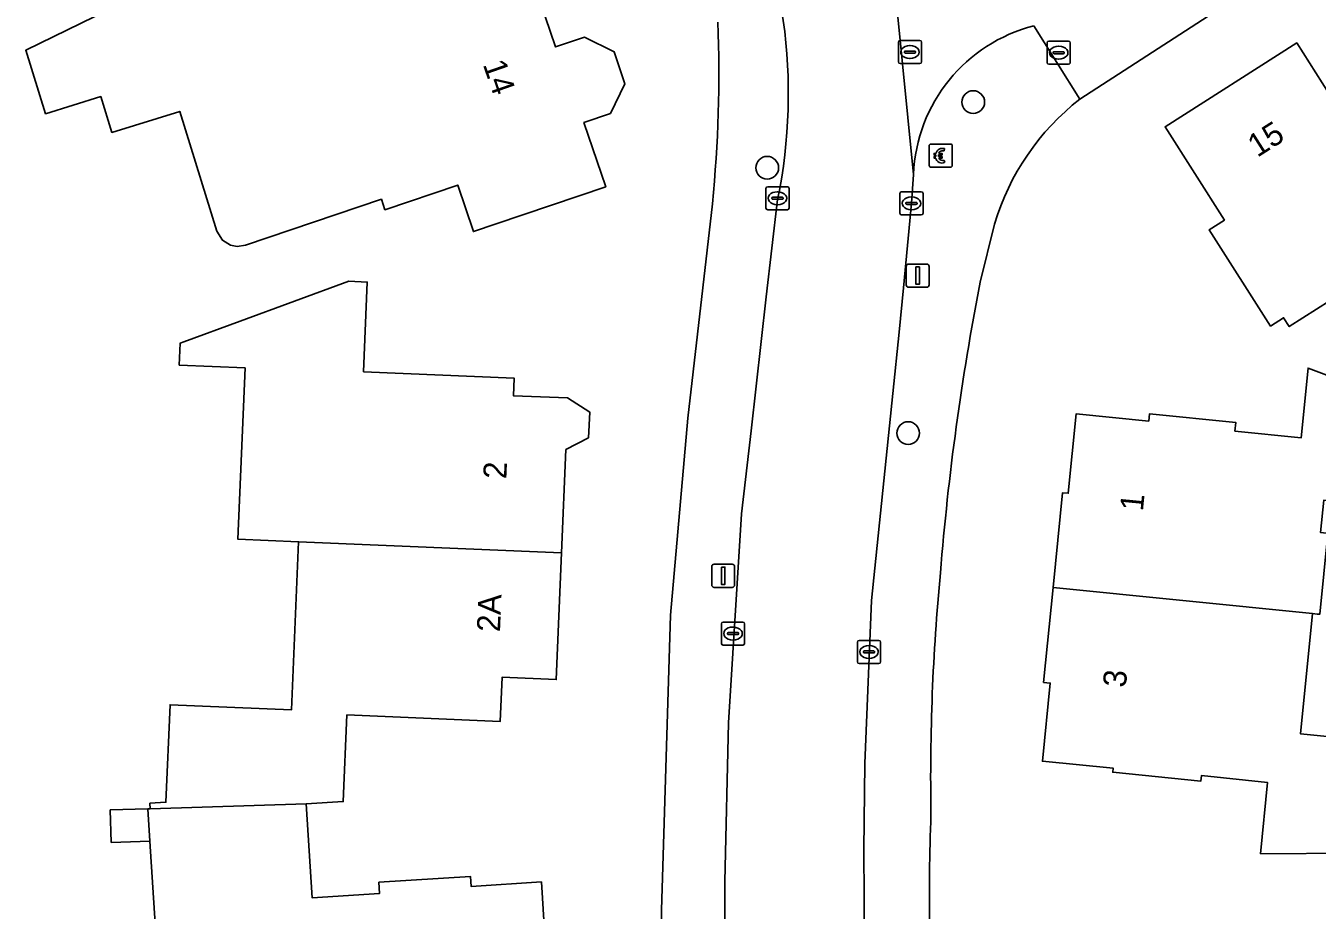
# Model space of a CAD drawing. Extents: x 161347 to 161881, y 382161 to 382804.
# Drawn here: x 161441.9 to 161497.7, y 382360.9 to 382399.1 of the extents above; entities that cross this region are included whole.
import ezdxf

# ---------------------------------------------------------------- set-up
doc = ezdxf.new("R2010")
doc.units = 0
for name, color, linetype in [('IMGEO_Betaalautomaat', 7, 'Continuous'), ('IMGEO_Boom', 7, 'Continuous'), ('IMGEO_Brandkraan', 7, 'Continuous'), ('IMGEO_Erf', 7, 'Continuous'), ('IMGEO_Kolk', 7, 'Continuous'), ('IMGEO_Lichtmast', 7, 'Continuous'), ('IMGEO_Pand', 7, 'Continuous'), ('IMGEO_Pand_nummerreeks', 7, 'Continuous'), ('IMGEO_Rijbaan_lokaal_open', 7, 'Continuous'), ('IMGEO_Rioolput', 7, 'Continuous'), ('IMGEO_Voetpad_open', 7, 'Continuous')]:
    doc.layers.add(name, color=color, linetype=linetype)

msp = doc.modelspace()

# ---------------------------------------------------------------- linework, layer by layer
at = {"layer": 'IMGEO_Betaalautomaat'}
for p, q in [((161481.039, 382393.984), (161481.88, 382393.984)), ((161481.88, 382393.984), (161481.039, 382393.984)), ((161480.964, 382393.06), (161480.964, 382393.901)), ((161480.964, 382393.901), (161480.964, 382393.06)), ((161481.247, 382393.448), (161481.247, 382393.516)), ((161481.368, 382393.516), (161481.368, 382393.448)), ((161481.626, 382393.789), (161481.609, 382393.689)), ((161481.963, 382393.91), (161481.963, 382393.069)), ((161481.963, 382393.069), (161481.963, 382393.91)), ((161481.889, 382392.985), (161481.048, 382392.985)), ((161481.048, 382392.985), (161481.889, 382392.985)), ((161481.613, 382393.283), (161481.635, 382393.196))]:
    msp.add_line(p, q, dxfattribs=at)
for points in [[(161481.247, 382393.516), (161481.178, 382393.516), (161481.178, 382393.585), (161481.257, 382393.585)], [(161481.252, 382393.379), (161481.178, 382393.379), (161481.178, 382393.448), (161481.247, 382393.448)], [(161481.379, 382393.585), (161481.526, 382393.585), (161481.526, 382393.516), (161481.368, 382393.516)], [(161481.368, 382393.448), (161481.526, 382393.448), (161481.526, 382393.379), (161481.382, 382393.379)]]:
    msp.add_lwpolyline(points, dxfattribs=at)
for centre, radius, start, end in [((161481.042, 382393.907), 0.0779, 92.4484, 184.2845), ((161481.042, 382393.907), 0.0779, 92.4484, 184.2845), ((161481.886, 382393.907), 0.0779, 2.4484, 94.2845), ((161481.886, 382393.907), 0.0779, 2.4484, 94.2845), ((161481.54, 382393.509), 0.293, 73.014, 165.0139), ((161481.546, 382393.522), 0.179, 69.3236, 159.5683), ((161481.042, 382393.063), 0.0779, 182.4484, 274.2845), ((161481.042, 382393.063), 0.0779, 182.4484, 274.2845), ((161481.513, 382393.434), 0.267, 191.8096, 297.0389), ((161481.546, 382393.449), 0.179, 202.7625, 291.8693), ((161481.886, 382393.063), 0.0779, 272.4484, 4.2845), ((161481.886, 382393.063), 0.0779, 272.4484, 4.2845)]:
    msp.add_arc(centre, radius, start, end, dxfattribs=at)
at = {"layer": 'IMGEO_Boom'}
for centre in [(161482.871, 382395.802), (161473.963, 382392.963), (161480.054, 382381.496)]:
    msp.add_circle(centre, 0.489, dxfattribs=at)
at = {"layer": 'IMGEO_Brandkraan'}
for p, q in [((161486.065, 382397.51), (161486.065, 382398.362)), ((161486.14, 382398.436), (161486.992, 382398.436)), ((161486.324, 382397.93), (161486.324, 382397.942)), ((161486.762, 382397.893), (161486.364, 382397.893)), ((161486.367, 382397.979), (161486.765, 382397.979)), ((161486.553, 382398.216), (161486.578, 382398.216)), ((161486.808, 382397.942), (161486.808, 382397.93)), ((161487.066, 382398.362), (161487.066, 382397.51)), ((161486.992, 382397.436), (161486.14, 382397.436)), ((161486.576, 382397.656), (161486.551, 382397.656))]:
    msp.add_line(p, q, dxfattribs=at)
for points in [[(161486.065, 382397.51), (161486.065, 382398.362)], [(161486.14, 382398.436), (161486.992, 382398.436)], [(161487.066, 382398.362), (161487.066, 382397.51)], [(161486.992, 382397.436), (161486.14, 382397.436)]]:
    msp.add_lwpolyline(points, dxfattribs=at)
for centre, radius, start, end in [((161486.142, 382398.36), 0.0765, 91.552, 178.448), ((161486.142, 382398.36), 0.0765, 91.552, 178.448), ((161486.364, 382397.939), 0.0403, 85.8775, 175.7526), ((161486.361, 382397.929), 0.0366, 178.938, 274.7102), ((161486.765, 382397.936), 0.043, 264.8664, 352.4533), ((161486.769, 382397.941), 0.0386, 1.7309, 96.639), ((161486.99, 382398.36), 0.0765, 1.552, 88.448), ((161486.99, 382398.36), 0.0765, 1.552, 88.448), ((161486.142, 382397.512), 0.0765, 181.552, 268.448), ((161486.142, 382397.512), 0.0765, 181.552, 268.448), ((161486.99, 382397.512), 0.0765, 271.552, 358.448), ((161486.99, 382397.512), 0.0765, 271.552, 358.448)]:
    msp.add_arc(centre, radius, start, end, dxfattribs=at)
for centre, major_axis, ratio, start_param, end_param in [((161486.552, 382397.936), (-0.387, 0.002), 0.722429, 4.712389, 7.853982), ((161486.577, 382397.936), (-0.39, 0.002), 0.717154, 1.570796, 4.712389)]:
    msp.add_ellipse(centre, major_axis=major_axis, ratio=ratio, start_param=start_param, end_param=end_param, dxfattribs=at)
at = {"layer": 'IMGEO_Erf'}
for points in [[(161617.144, 382396.335), (161617.418, 382397.853), (161603.267, 382420.926), (161601.482, 382423.837), (161585.851, 382449.323), (161572.419, 382451.387), (161564.764, 382446.042), (161558.459, 382441.915), (161500, 382404.037), (161487.478, 382395.924)], [(161463.01, 382403.497), (161464.811, 382398.182), (161466.063, 382398.606), (161467.338, 382397.976), (161467.81, 382396.584), (161467.178, 382395.304), (161466.037, 382394.917), (161466.977, 382392.145), (161462.242, 382390.54), (161461.258, 382390.207), (161460.577, 382392.215), (161457.433, 382391.149), (161457.279, 382391.604), (161451.403, 382389.612), (161451.041, 382389.561), (161450.751, 382389.62), (161450.413, 382389.832), (161450.165, 382390.222), (161448.556, 382395.4), (161445.624, 382394.489), (161445.143, 382396.036), (161442.756, 382395.294), (161441.902, 382398.039), (161450.849, 382402.431)], [(161469.78, 382373.623), (161470.522, 382382.134), (161471.59, 382391.404)], [(161483.786, 382390.531), (161483.173, 382388.018)], [(161447.592, 382358.746), (161447.271, 382363.854), (161445.597, 382363.802), (161445.553, 382365.206), (161447.183, 382365.257), (161447.284, 382365.26), (161447.269, 382365.496), (161447.96, 382365.539), (161448.137, 382369.757), (161453.394, 382369.537), (161453.698, 382376.796), (161451.074, 382376.906), (161451.384, 382384.314), (161448.535, 382384.433), (161448.575, 382385.375), (161448.732, 382385.433), (161451.176, 382386.331), (161455.869, 382388.055), (161456.668, 382388.021), (161456.505, 382384.145), (161463.018, 382383.871), (161462.986, 382383.112), (161465.323, 382383.015), (161466.284, 382382.404), (161466.237, 382381.297), (161465.256, 382380.784), (161465.07, 382376.321), (161464.842, 382370.842), (161462.497, 382370.94), (161462.417, 382369.037), (161455.784, 382369.315), (161455.627, 382365.57), (161454.029, 382365.47), (161454.282, 382361.415), (161457.201, 382361.599), (161457.17, 382362.086), (161461.129, 382362.334), (161461.156, 382361.903), (161464.198, 382362.095), (161464.435, 382358.327)], [(161499.257, 382363.337), (161495.296, 382363.317), (161495.599, 382366.388), (161492.736, 382366.691), (161492.712, 382366.457), (161488.905, 382366.837), (161488.922, 382367.007), (161485.86, 382367.313), (161486.198, 382370.692), (161485.914, 382370.72), (161486.324, 382374.818), (161486.734, 382378.916), (161486.978, 382378.892), (161487.322, 382382.33), (161490.457, 382382.017), (161490.488, 382382.326), (161494.22, 382381.953), (161494.183, 382381.583), (161497.046, 382381.288), (161497.352, 382384.306), (161500, 382383.308)], [(161469.389, 382360.877), (161469.78, 382373.623)], [(161497.793, 382373.671), (161497.741, 382373.676), (161497.542, 382373.696), (161497.022, 382368.493), (161499.745, 382368.221)]]:
    msp.add_lwpolyline(points, dxfattribs=at)
msp.add_lwpolyline([(161502.083, 382392.021), (161504.368, 382388.437), (161502.582, 382387.27), (161500.724, 382386.056), (161500, 382387.174), (161499.482, 382387.974), (161496.532, 382386.095), (161496.289, 382386.477), (161495.731, 382386.121), (161493.078, 382390.285), (161493.735, 382390.704), (161491.166, 382394.735), (161496.857, 382398.36), (161498.783, 382395.337), (161500, 382396.112), (161500.681, 382396.546), (161503.137, 382392.692)], close=True, dxfattribs=at)
for centre, radius, start, end in [((161415.607, 382397.014), 56.263, 354.2771, 2.2772), ((161494.127, 382387.412), 10.801, 127.9943, 163.2153), ((161593.048, 382366.576), 111.948, 168.95745, 175.45076), ((161573.502, 382366.61), 92.473, 174.51109, 180.99743), ((161557.326, 382361.781), 76.351, 177.58362, 185.0968), ((161553.635, 382359.287), 84.261, 178.91872, 187.12135)]:
    msp.add_arc(centre, radius, start, end, dxfattribs=at)
at = {"layer": 'IMGEO_Kolk'}
for p, q in [((161473.906, 382391.218), (161473.906, 382392.07)), ((161473.981, 382392.144), (161474.833, 382392.144)), ((161474.394, 382391.924), (161474.419, 382391.924)), ((161474.907, 382392.07), (161474.907, 382391.218)), ((161479.697, 382390.998), (161479.697, 382391.85)), ((161479.772, 382391.924), (161480.624, 382391.924)), ((161480.698, 382391.85), (161480.698, 382390.998)), ((161474.165, 382391.638), (161474.165, 382391.65)), ((161474.603, 382391.601), (161474.205, 382391.601)), ((161474.208, 382391.687), (161474.606, 382391.687)), ((161474.417, 382391.364), (161474.392, 382391.364)), ((161474.649, 382391.65), (161474.649, 382391.638)), ((161479.956, 382391.418), (161479.956, 382391.43)), ((161480.394, 382391.381), (161479.996, 382391.381)), ((161479.999, 382391.467), (161480.397, 382391.467)), ((161480.185, 382391.704), (161480.21, 382391.704)), ((161480.44, 382391.43), (161480.44, 382391.418)), ((161474.833, 382391.144), (161473.981, 382391.144)), ((161480.624, 382390.924), (161479.772, 382390.924)), ((161480.208, 382391.144), (161480.183, 382391.144)), ((161472.058, 382373.33), (161472.91, 382373.33)), ((161471.983, 382372.404), (161471.983, 382373.256)), ((161472.242, 382372.824), (161472.242, 382372.836)), ((161472.68, 382372.787), (161472.282, 382372.787)), ((161472.285, 382372.873), (161472.683, 382372.873)), ((161472.471, 382373.11), (161472.496, 382373.11)), ((161472.726, 382372.836), (161472.726, 382372.824)), ((161472.984, 382373.256), (161472.984, 382372.404)), ((161472.91, 382372.33), (161472.058, 382372.33)), ((161472.494, 382372.55), (161472.469, 382372.55)), ((161477.863, 382371.61), (161477.863, 382372.462)), ((161477.938, 382372.536), (161478.79, 382372.536)), ((161478.351, 382372.316), (161478.376, 382372.316)), ((161478.864, 382372.462), (161478.864, 382371.61)), ((161478.122, 382372.03), (161478.122, 382372.042)), ((161478.56, 382371.993), (161478.162, 382371.993)), ((161478.165, 382372.079), (161478.563, 382372.079)), ((161478.374, 382371.756), (161478.349, 382371.756)), ((161478.606, 382372.042), (161478.606, 382372.03)), ((161478.79, 382371.536), (161477.938, 382371.536))]:
    msp.add_line(p, q, dxfattribs=at)
for points in [[(161473.906, 382391.218), (161473.906, 382392.07)], [(161473.981, 382392.144), (161474.833, 382392.144)], [(161474.907, 382392.07), (161474.907, 382391.218)], [(161479.697, 382390.998), (161479.697, 382391.85)], [(161479.772, 382391.924), (161480.624, 382391.924)], [(161480.698, 382391.85), (161480.698, 382390.998)], [(161474.833, 382391.144), (161473.981, 382391.144)], [(161480.624, 382390.924), (161479.772, 382390.924)], [(161472.058, 382373.33), (161472.91, 382373.33)], [(161471.983, 382372.404), (161471.983, 382373.256)], [(161472.984, 382373.256), (161472.984, 382372.404)], [(161472.91, 382372.33), (161472.058, 382372.33)], [(161477.863, 382371.61), (161477.863, 382372.462)], [(161477.938, 382372.536), (161478.79, 382372.536)], [(161478.864, 382372.462), (161478.864, 382371.61)], [(161478.79, 382371.536), (161477.938, 382371.536)]]:
    msp.add_lwpolyline(points, dxfattribs=at)
for centre, radius, start, end in [((161473.983, 382392.068), 0.0765, 91.552, 178.448), ((161473.983, 382392.068), 0.0765, 91.552, 178.448), ((161474.831, 382392.068), 0.0765, 1.552, 88.448), ((161474.831, 382392.068), 0.0765, 1.552, 88.448), ((161479.774, 382391.848), 0.0765, 91.552, 178.448), ((161479.774, 382391.848), 0.0765, 91.552, 178.448), ((161480.622, 382391.848), 0.0765, 1.552, 88.448), ((161480.622, 382391.848), 0.0765, 1.552, 88.448), ((161473.983, 382391.22), 0.0765, 181.552, 268.448), ((161473.983, 382391.22), 0.0765, 181.552, 268.448), ((161474.205, 382391.647), 0.0403, 85.8775, 175.7526), ((161474.202, 382391.637), 0.0366, 178.938, 274.7102), ((161474.606, 382391.644), 0.043, 264.8664, 352.4533), ((161474.61, 382391.649), 0.0386, 1.7309, 96.639), ((161474.831, 382391.22), 0.0765, 271.552, 358.448), ((161474.831, 382391.22), 0.0765, 271.552, 358.448), ((161479.996, 382391.427), 0.0403, 85.8775, 175.7526), ((161479.993, 382391.417), 0.0366, 178.938, 274.7102), ((161480.397, 382391.424), 0.043, 264.8664, 352.4533), ((161480.401, 382391.429), 0.0386, 1.7309, 96.639), ((161479.774, 382391), 0.0765, 181.552, 268.448), ((161479.774, 382391), 0.0765, 181.552, 268.448), ((161480.622, 382391), 0.0765, 271.552, 358.448), ((161480.622, 382391), 0.0765, 271.552, 358.448), ((161472.06, 382373.254), 0.0765, 91.552, 178.448), ((161472.06, 382373.254), 0.0765, 91.552, 178.448), ((161472.908, 382373.254), 0.0765, 1.552, 88.448), ((161472.908, 382373.254), 0.0765, 1.552, 88.448), ((161472.282, 382372.833), 0.0403, 85.8775, 175.7526), ((161472.279, 382372.823), 0.0366, 178.938, 274.7102), ((161472.683, 382372.83), 0.043, 264.8664, 352.4533), ((161472.687, 382372.835), 0.0386, 1.7309, 96.639), ((161472.06, 382372.406), 0.0765, 181.552, 268.448), ((161472.06, 382372.406), 0.0765, 181.552, 268.448), ((161472.908, 382372.406), 0.0765, 271.552, 358.448), ((161472.908, 382372.406), 0.0765, 271.552, 358.448), ((161477.94, 382372.46), 0.0765, 91.552, 178.448), ((161477.94, 382372.46), 0.0765, 91.552, 178.448), ((161478.788, 382372.46), 0.0765, 1.552, 88.448), ((161478.788, 382372.46), 0.0765, 1.552, 88.448), ((161478.162, 382372.039), 0.0403, 85.8775, 175.7526), ((161478.159, 382372.029), 0.0366, 178.938, 274.7102), ((161478.563, 382372.036), 0.043, 264.8664, 352.4533), ((161478.567, 382372.041), 0.0386, 1.7309, 96.639), ((161477.94, 382371.612), 0.0765, 181.552, 268.448), ((161477.94, 382371.612), 0.0765, 181.552, 268.448), ((161478.788, 382371.612), 0.0765, 271.552, 358.448), ((161478.788, 382371.612), 0.0765, 271.552, 358.448)]:
    msp.add_arc(centre, radius, start, end, dxfattribs=at)
for centre, major_axis, ratio, start_param, end_param in [((161474.393, 382391.644), (-0.387, 0.002), 0.722429, 4.712389, 7.853982), ((161474.418, 382391.644), (-0.39, 0.002), 0.717154, 1.570796, 4.712389), ((161480.184, 382391.424), (-0.387, 0.002), 0.722429, 4.712389, 7.853982), ((161480.209, 382391.424), (-0.39, 0.002), 0.717154, 1.570796, 4.712389), ((161472.47, 382372.83), (-0.387, 0.002), 0.722429, 4.712389, 7.853982), ((161472.495, 382372.83), (-0.39, 0.002), 0.717154, 1.570796, 4.712389), ((161478.35, 382372.036), (-0.387, 0.002), 0.722429, 4.712389, 7.853982), ((161478.375, 382372.036), (-0.39, 0.002), 0.717154, 1.570796, 4.712389)]:
    msp.add_ellipse(centre, major_axis=major_axis, ratio=ratio, start_param=start_param, end_param=end_param, dxfattribs=at)
at = {"layer": 'IMGEO_Lichtmast'}
for p, q in [((161479.973, 382387.9), (161479.973, 382388.7)), ((161479.973, 382388.7), (161479.973, 382387.9)), ((161480.073, 382388.8), (161480.863, 382388.8)), ((161480.863, 382388.8), (161480.073, 382388.8)), ((161480.963, 382388.7), (161480.963, 382387.9)), ((161480.963, 382387.9), (161480.963, 382388.7)), ((161480.863, 382387.8), (161480.073, 382387.8)), ((161480.073, 382387.8), (161480.863, 382387.8)), ((161471.562, 382374.929), (161471.562, 382375.729)), ((161471.562, 382375.729), (161471.562, 382374.929)), ((161471.662, 382375.829), (161472.452, 382375.829)), ((161472.452, 382375.829), (161471.662, 382375.829)), ((161472.552, 382375.729), (161472.552, 382374.929)), ((161472.552, 382374.929), (161472.552, 382375.729)), ((161472.452, 382374.829), (161471.662, 382374.829)), ((161471.662, 382374.829), (161472.452, 382374.829))]:
    msp.add_line(p, q, dxfattribs=at)
for points in [[(161480.393, 382388.675), (161480.543, 382388.675), (161480.543, 382387.925), (161480.393, 382387.925), (161480.393, 382388.675)], [(161471.982, 382375.704), (161472.132, 382375.704), (161472.132, 382374.954), (161471.982, 382374.954), (161471.982, 382375.704)]]:
    msp.add_lwpolyline(points, dxfattribs=at)
for centre, start, end in [((161480.073, 382388.7), 90, 180), ((161480.073, 382388.7), 90, 180), ((161480.863, 382388.7), 0, 90), ((161480.863, 382388.7), 360, 90), ((161480.073, 382387.9), 180, 270), ((161480.073, 382387.9), 180, 270), ((161480.863, 382387.9), 270, 0), ((161480.863, 382387.9), 270, 0), ((161471.662, 382375.729), 90, 180), ((161471.662, 382375.729), 90, 180), ((161472.452, 382375.729), 0, 90), ((161472.452, 382375.729), 360, 90), ((161471.662, 382374.929), 180, 270), ((161471.662, 382374.929), 180, 270), ((161472.452, 382374.929), 270, 0), ((161472.452, 382374.929), 270, 0)]:
    msp.add_arc(centre, 0.1, start, end, dxfattribs=at)
at = {"layer": 'IMGEO_Pand'}
msp.add_lwpolyline([(161450.849, 382402.431), (161441.902, 382398.039), (161442.756, 382395.294), (161445.143, 382396.036), (161445.624, 382394.489), (161448.556, 382395.4), (161450.165, 382390.222), (161450.413, 382389.832), (161450.751, 382389.62), (161451.041, 382389.561), (161451.403, 382389.612), (161457.279, 382391.604), (161457.433, 382391.149), (161460.577, 382392.215), (161461.258, 382390.207), (161462.242, 382390.54), (161466.977, 382392.145), (161466.037, 382394.917), (161467.178, 382395.304), (161467.81, 382396.584), (161467.338, 382397.976), (161466.063, 382398.606), (161464.811, 382398.182), (161463.01, 382403.497)], dxfattribs=at)
for points in [[(161503.137, 382392.692), (161500.681, 382396.546), (161500, 382396.112), (161498.783, 382395.337), (161496.857, 382398.36), (161491.166, 382394.735), (161493.735, 382390.704), (161493.078, 382390.285), (161495.731, 382386.121), (161496.289, 382386.477), (161496.532, 382386.095), (161499.482, 382387.974), (161500, 382387.174), (161500.724, 382386.056), (161502.582, 382387.27), (161504.368, 382388.437), (161502.083, 382392.021)], [(161463.018, 382383.871), (161456.505, 382384.145), (161456.668, 382388.021), (161455.869, 382388.055), (161451.176, 382386.331), (161448.732, 382385.433), (161448.575, 382385.375), (161448.535, 382384.433), (161451.384, 382384.314), (161451.074, 382376.906), (161453.698, 382376.796), (161465.07, 382376.321), (161465.256, 382380.784), (161466.237, 382381.297), (161466.284, 382382.404), (161465.323, 382383.015), (161462.986, 382383.112)], [(161501.136, 382382.88), (161500, 382383.308), (161497.352, 382384.306), (161497.046, 382381.288), (161494.183, 382381.583), (161494.22, 382381.953), (161490.488, 382382.326), (161490.457, 382382.017), (161487.322, 382382.33), (161486.978, 382378.892), (161486.734, 382378.916), (161486.324, 382374.818), (161497.542, 382373.696), (161497.741, 382373.676), (161497.793, 382373.671), (161497.852, 382373.665), (161498.203, 382377.162), (161498.144, 382377.168), (161497.892, 382377.195), (161498.033, 382378.6), (161500, 382378.387), (161500.691, 382378.312)], [(161465.07, 382376.321), (161453.698, 382376.796), (161453.394, 382369.537), (161448.137, 382369.757), (161447.96, 382365.539), (161447.269, 382365.496), (161447.284, 382365.26), (161454.029, 382365.47), (161455.627, 382365.57), (161455.784, 382369.315), (161462.417, 382369.037), (161462.497, 382370.94), (161464.842, 382370.842)], [(161486.324, 382374.818), (161485.914, 382370.72), (161486.198, 382370.692), (161485.86, 382367.313), (161488.922, 382367.007), (161488.905, 382366.837), (161492.712, 382366.457), (161492.736, 382366.691), (161495.599, 382366.388), (161495.296, 382363.317), (161499.257, 382363.337), (161499.745, 382368.221), (161497.022, 382368.493), (161497.542, 382373.696)], [(161447.183, 382365.257), (161445.553, 382365.206), (161445.597, 382363.802), (161447.271, 382363.854)], [(161454.029, 382365.47), (161447.284, 382365.26), (161447.183, 382365.257), (161447.271, 382363.854), (161447.592, 382358.746), (161447.699, 382358.647), (161448.456, 382357.949), (161451.747, 382358.156), (161452, 382354.124), (161454.377, 382354.255), (161464.698, 382354.898), (161464.645, 382355.738), (161465.298, 382356.172), (161465.186, 382357.953), (161464.435, 382358.327), (161464.198, 382362.095), (161461.156, 382361.903), (161461.129, 382362.334), (161457.17, 382362.086), (161457.201, 382361.599), (161454.282, 382361.415)]]:
    msp.add_lwpolyline(points, close=True, dxfattribs=at)
at = {"layer": 'IMGEO_Rijbaan_lokaal_open'}
for points in [[(161478.141, 382363.489), (161478.179, 382367.212), (161478.467, 382374.26), (161479.39, 382383.203), (161479.664, 382385.857), (161479.848, 382387.77), (161480.126, 382390.67), (161480.197, 382391.427), (161480.29, 382392.675), (161478.84, 382407.183)], [(161478.84, 382407.183), (161480.29, 382392.675)], [(161474.412, 382391.584), (161473.921, 382387.39), (161473.27, 382381.594), (161472.852, 382378.01), (161472.288, 382368.966), (161472.129, 382362.118)], [(161478.913, 382349.703), (161478.847, 382350.23), (161478.529, 382353.479), (161478.171, 382359.336), (161478.141, 382363.489)]]:
    msp.add_lwpolyline(points, dxfattribs=at)
for centre, radius, start, end in [((161451.842, 382396.174), 23.032, 348.5059, 27.2322), ((161487.188, 382392.403), 6.903, 104.1787, 177.7418), ((161565.952, 382361.125), 93.828, 179.39336, 187.11372)]:
    msp.add_arc(centre, radius, start, end, dxfattribs=at)
at = {"layer": 'IMGEO_Rioolput'}
for p, q in [((161479.708, 382398.465), (161480.56, 382398.465)), ((161479.633, 382397.539), (161479.633, 382398.391)), ((161479.892, 382397.959), (161479.892, 382397.971)), ((161480.33, 382397.922), (161479.932, 382397.922)), ((161479.935, 382398.008), (161480.333, 382398.008)), ((161480.121, 382398.245), (161480.146, 382398.245)), ((161480.376, 382397.971), (161480.376, 382397.959)), ((161480.634, 382398.391), (161480.634, 382397.539)), ((161480.56, 382397.465), (161479.708, 382397.465)), ((161480.144, 382397.685), (161480.119, 382397.685))]:
    msp.add_line(p, q, dxfattribs=at)
for points in [[(161479.708, 382398.465), (161480.56, 382398.465)], [(161479.633, 382397.539), (161479.633, 382398.391)], [(161480.634, 382398.391), (161480.634, 382397.539)], [(161480.56, 382397.465), (161479.708, 382397.465)]]:
    msp.add_lwpolyline(points, dxfattribs=at)
for centre, radius, start, end in [((161479.71, 382398.389), 0.0765, 91.552, 178.448), ((161479.71, 382398.389), 0.0765, 91.552, 178.448), ((161480.558, 382398.389), 0.0765, 1.552, 88.448), ((161480.558, 382398.389), 0.0765, 1.552, 88.448), ((161479.932, 382397.968), 0.0403, 85.8775, 175.7526), ((161479.929, 382397.958), 0.0366, 178.938, 274.7102), ((161480.333, 382397.965), 0.043, 264.8664, 352.4533), ((161480.337, 382397.97), 0.0386, 1.7309, 96.639), ((161479.71, 382397.541), 0.0765, 181.552, 268.448), ((161479.71, 382397.541), 0.0765, 181.552, 268.448), ((161480.558, 382397.541), 0.0765, 271.552, 358.448), ((161480.558, 382397.541), 0.0765, 271.552, 358.448)]:
    msp.add_arc(centre, radius, start, end, dxfattribs=at)
for centre, major_axis, ratio, start_param, end_param in [((161480.12, 382397.965), (-0.387, 0.002), 0.722429, 4.712389, 7.853982), ((161480.145, 382397.965), (-0.39, 0.002), 0.717154, 1.570796, 4.712389)]:
    msp.add_ellipse(centre, major_axis=major_axis, ratio=ratio, start_param=start_param, end_param=end_param, dxfattribs=at)
at = {"layer": 'IMGEO_Voetpad_open'}
for points in [[(161485.497, 382399.096), (161487.478, 382395.924), (161500, 382404.037), (161558.459, 382441.915)], [(161487.478, 382395.924), (161485.497, 382399.096)], [(161480.29, 382392.675), (161480.197, 382391.427), (161480.126, 382390.67), (161479.848, 382387.77), (161479.664, 382385.857), (161479.39, 382383.203), (161478.467, 382374.26), (161478.179, 382367.212), (161478.141, 382363.489), (161478.171, 382359.336), (161478.529, 382353.479), (161478.847, 382350.23), (161478.913, 382349.703)], [(161471.59, 382391.404), (161470.522, 382382.134), (161469.78, 382373.623), (161469.389, 382360.877)], [(161472.129, 382362.118), (161472.288, 382368.966), (161472.852, 382378.01), (161473.27, 382381.594), (161473.921, 382387.39), (161474.412, 382391.584)], [(161483.173, 382388.018), (161483.786, 382390.531)]]:
    msp.add_lwpolyline(points, dxfattribs=at)
for centre, radius, start, end in [((161451.842, 382396.174), 23.032, 348.5059, 27.2322), ((161415.607, 382397.014), 56.263, 354.2771, 2.2772), ((161487.188, 382392.403), 6.903, 104.1787, 177.7418), ((161494.127, 382387.412), 10.801, 127.9943, 163.2153), ((161593.048, 382366.576), 111.948, 168.95745, 175.45076), ((161573.502, 382366.61), 92.473, 174.51109, 180.99743), ((161557.326, 382361.781), 76.351, 177.58362, 185.0968), ((161565.952, 382361.125), 93.828, 179.39336, 187.11372), ((161553.635, 382359.287), 84.261, 178.91872, 187.12135)]:
    msp.add_arc(centre, radius, start, end, dxfattribs=at)

# ---------------------------------------------------------------- texts
at = {"layer": 'IMGEO_Pand_nummerreeks'}
for s, rotation, p in [('14', 289.2622, (161461.655, 382397.432)), ('15', 32.4959, (161495.153, 382393.387)), ('2', 87.6167, (161462.68, 382379.495)), ('1', 84.4368, (161490.206, 382378.098)), ('2A', 87.6155, (161462.405, 382372.883)), ('3', 84.4394, (161489.464, 382370.475))]:
    msp.add_text(s, height=1, rotation=rotation, dxfattribs=at).set_placement(p)

doc.saveas('drawing.dxf')
